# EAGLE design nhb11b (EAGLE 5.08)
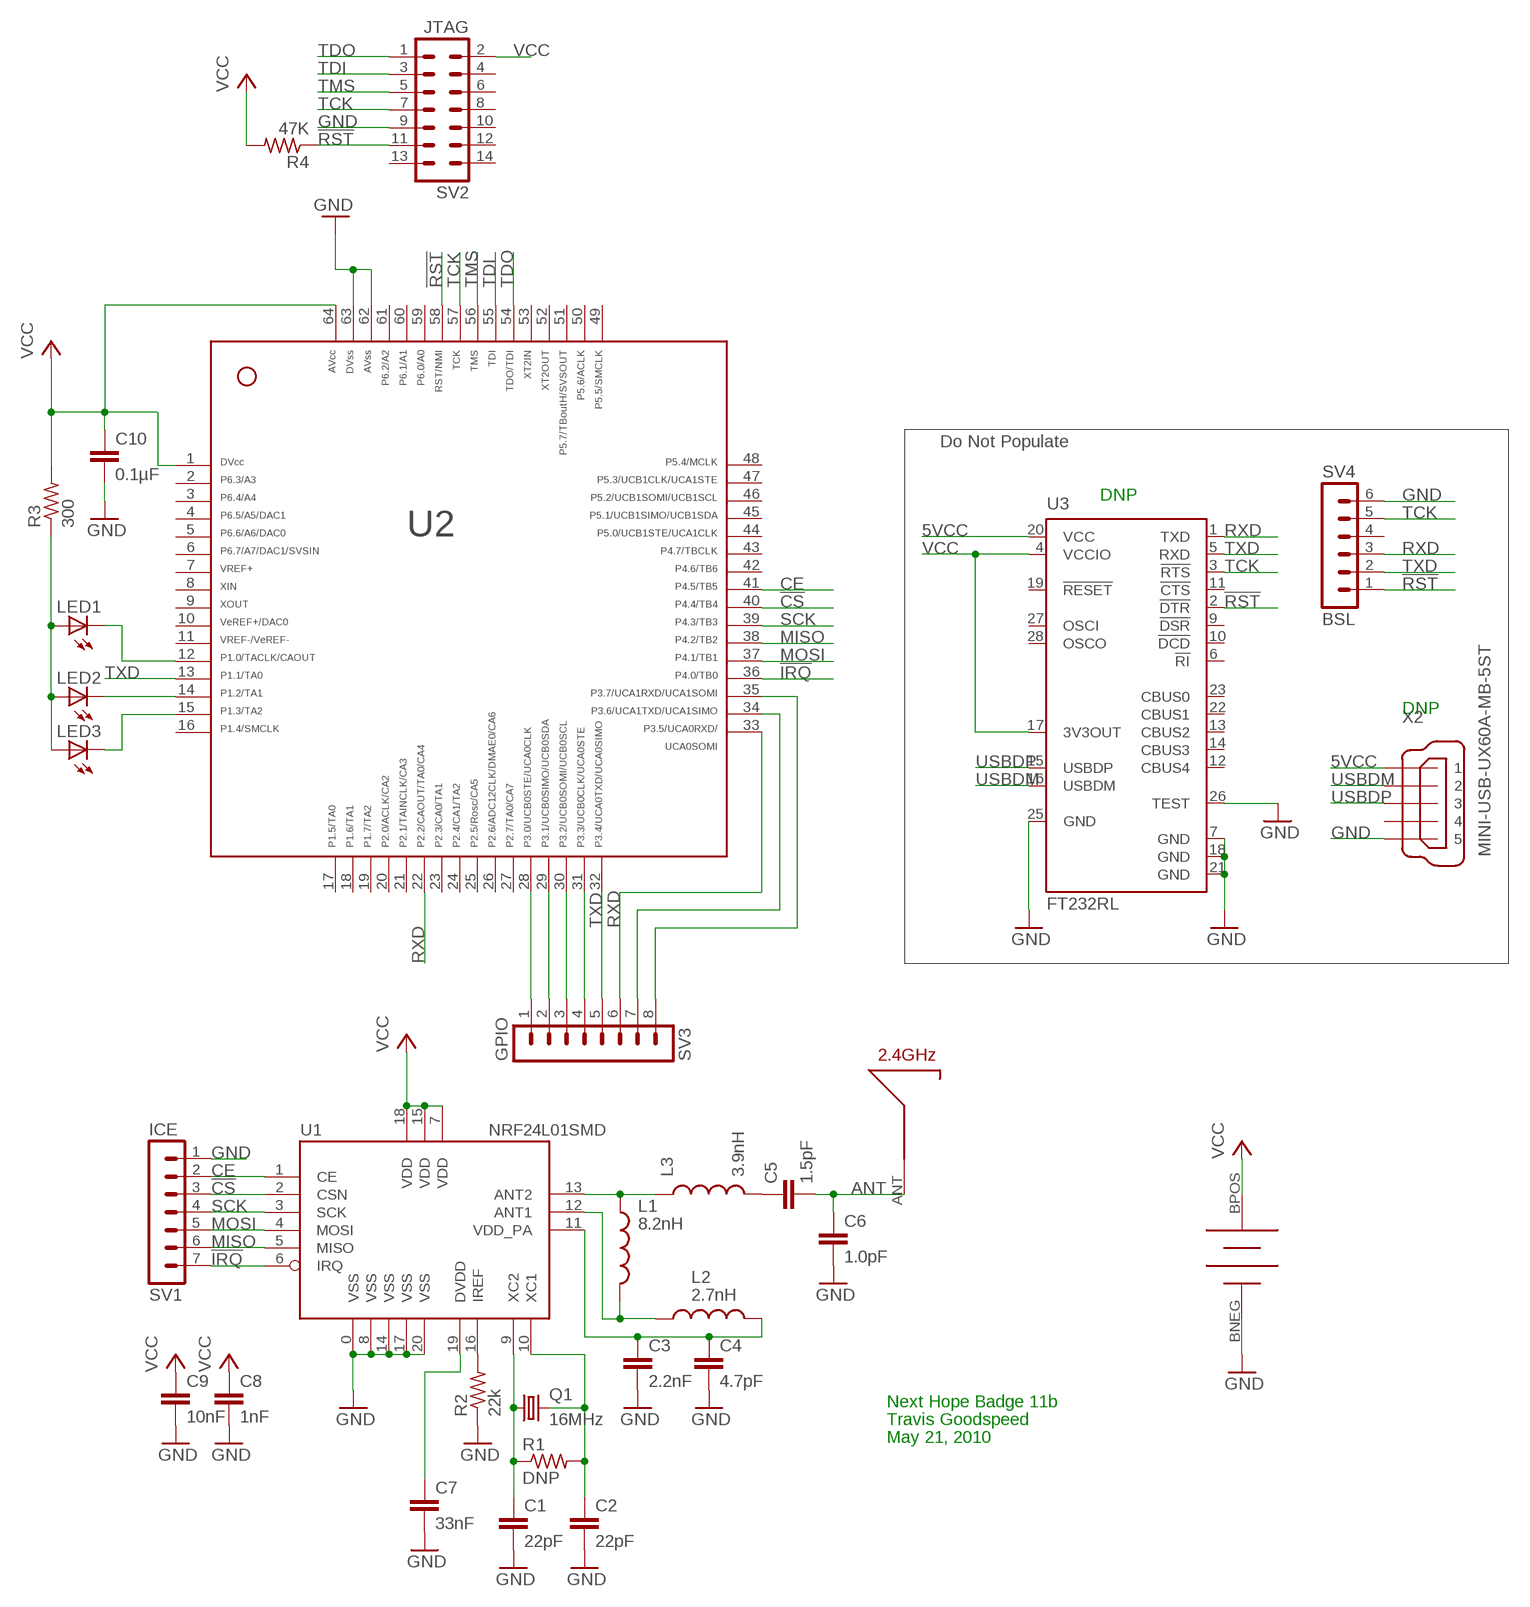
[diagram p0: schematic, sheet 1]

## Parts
C1  22pF  C-EUC0603  [C0603]
C2  22pF  C-EUC0603  [C0603]
C3  2.2nF  C-EUC0603  [C0603]
C4  4.7pF  C-EUC0603  [C0603]
C5  1.5pF  C-EUC0603  [C0603]
C6  1.0pF  C-EUC0603  [C0603]
C7  33nF  C-EUC0603  [C0603]
C8  1nF  C-EUC0603  [C0603]
C9  10nF  C-EUC0603  [C0603]
C10  0.1µF  C-EUC0603  [C0603]
L1  8.2nH  INDUCTOR0603  [0603]
L2  2.7nH  INDUCTOR0603  [0603]
L3  3.9nH  INDUCTOR0603  [0603]
LED1  LEDCHIPLED_0603  [CHIPLED_0603]
LED2  LEDCHIPLED_0603  [CHIPLED_0603]
LED3  LEDCHIPLED_0603  [CHIPLED_0603]
Q1  16MHz  CRYSTALSM49  [SM49]
R1  DNP  R-US_R0603  [R0603]
R2  22k  R-US_R0603  [R0603]
R3  300  R-US_R0603  [R0603]
R4  47K  R-US_R0603  [R0603]
SV1  ICE  MA07-1  [MA07-1]
SV2  JTAG  MA07-2  [MA07-2]
SV3  GPIO  MA08-1  [MA08-1]
SV4  BSL  MA06-1  [MA06-1]
U1  NRF24L01SMD  [QFN20]
U2  F261X---PM64  [PM/PAG64]
U3  FT232RL  [SSOP28]
U$1  CR2032  [CR2032]
U$2  ANT24  [ANT24]
X2  MINI-USB-UX60A-MB-5ST  [UX60A-MB-5ST]

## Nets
5VCC: U3.20(VCC) X2.1
!CS: SV1.3 U1.2(CSN) U2.40
!IRQ: SV1.7 U1.6(IRQ) U2.36
!RST: R4.1 SV2.11 SV4.1 U2.58 U3.2(!DTR)
ANT: C5.2 C6.1 U$2.ANT
CE: SV1.2 U1.1(CE) U2.41
GND: C1.2 C2.2 C3.2 C4.2 C6.2 C7.2 C8.2 C9.2 C10.2 R2.1 SV1.1 SV2.9 SV4.6 U1.0(VSS) U1.8(VSS) U1.14(VSS) U1.17(VSS) U1.20(VSS) U2.62 U2.63 U3.7(GND) U3.18(GND) U3.21(GND) U3.25(GND) U3.26(TEST) U$1.BNEG(BATGND) X2.5
MISO: SV1.6 U1.5(MISO) U2.38
MOSI: SV1.5 U1.4(MOSI) U2.37
N$1: C1.1 Q1.1 R1.1 U1.9(XC2)
N$2: C2.1 Q1.2 R1.2 U1.10(XC1)
N$3: R2.2 U1.16(IREF)
N$4: C7.1 U1.19(DVDD)
N$5: C3.1 C4.1 L2.2 U1.11(VDD_PA)
N$6: C5.1 L3.2
N$7: L1.2 L2.1 U1.12(ANT1)
N$8: SV3.1 U2.28
N$9: L1.1 L3.1 U1.13(ANT2)
N$10: LED1.A LED2.A LED3.A R3.1
N$11: SV3.2 U2.29
N$12: LED1.C U2.12
N$13: LED3.C U2.15
N$14: LED2.C U2.14
N$15: SV3.3 U2.30
N$16: SV3.4 U2.31
N$19: SV3.7 U2.34
N$23: SV3.8 U2.35
RXD: SV3.6 SV4.3 U2.22 U2.33 U3.1(TXD)
SCK: SV1.4 U1.3(SCK) U2.39
TCK: SV2.7 SV4.5 U2.57 U3.3(!RTS)
TDI: SV2.3 U2.55
TDO: SV2.1 U2.54
TMS: SV2.5 U2.56
TXD: SV3.5 SV4.2 U2.13 U2.32 U3.5(RXD)
USBDM: U3.16(USBDM) X2.2
USBDP: U3.15(USBDP) X2.3
VCC: C8.1 C9.1 C10.1 R3.2 R4.2 SV2.2 U1.7(VDD) U1.15(VDD) U1.18(VDD) U2.1 U2.64 U3.4(VCCIO) U3.17(3V3OUT) U$1.BPOS(BATVCC)
Unconnected: SV2.4 SV2.6 SV2.8 SV2.10 SV2.12 SV2.13 SV2.14 SV4.4 U2.2 U2.3 U2.4 U2.5 U2.6 U2.7 U2.8 U2.9 U2.10 U2.11 U2.16 U2.17 U2.18 U2.19 U2.20 U2.21 U2.23 U2.24 U2.25 U2.26 U2.27 U2.42 U2.43 U2.44 U2.45 U2.46 U2.47 U2.48 U2.49 U2.50 U2.51 U2.52 U2.53 U2.59 U2.60 U2.61 U3.6(!RI) U3.9(!DSR) U3.10(!DCD) U3.11(!CTS) U3.12(CBUS4) U3.13(CBUS2) U3.14(CBUS3) U3.19(!RESET) U3.22(CBUS1) U3.23(CBUS0) U3.27(OSCI) U3.28(OSCO) X2.4

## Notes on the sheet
- Do Not Populate
- DNP
- DNP
- Next Hope Badge 11b
- Travis Goodspeed
- May 21, 2010

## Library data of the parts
C1-C10 = rcl:C-EU: CAPACITOR, European symbol
L1-L3 = SparkFun:INDUCTOR: Inductors
LED1-LED3 = led:LED: LED
Q1 = crystal:CRYSTAL: CRYSTAL
R1-R4 = rcl:R-US_: RESISTOR, American symbol
SV1 = con-lstb:MA07-1: PIN HEADER
SV2 = con-lstb:MA07-2: PIN HEADER
SV3 = con-lstb:MA08-1: PIN HEADER
SV4 = con-lstb:MA06-1: PIN HEADER
U1 = SparkFun:NRF24L01: 2.4GHz Low Power Transceiver This is the very popular, low cost, very low power RF transceiver from Nordic Semiconductor. Simple SPI interface. SKU: COM-00690
U2 = TI_MSP430_v13:F261X---PM64: ***MSP430F261x***PM64
U3 = ftdichip:FT232R: Source: http://www.ftdichip.com/Documents/DataSheets/DS_FT232R_v104.pdf
U$1 = nhb:CR2032
U$2 = nhb:ANT24: 2.45GHz trace antenna.
X2 = con-hirose:MINI-USB-: MINI USB Connector Source: http://www.hirose.co.jp/cataloge_hp/e24000019.pdf

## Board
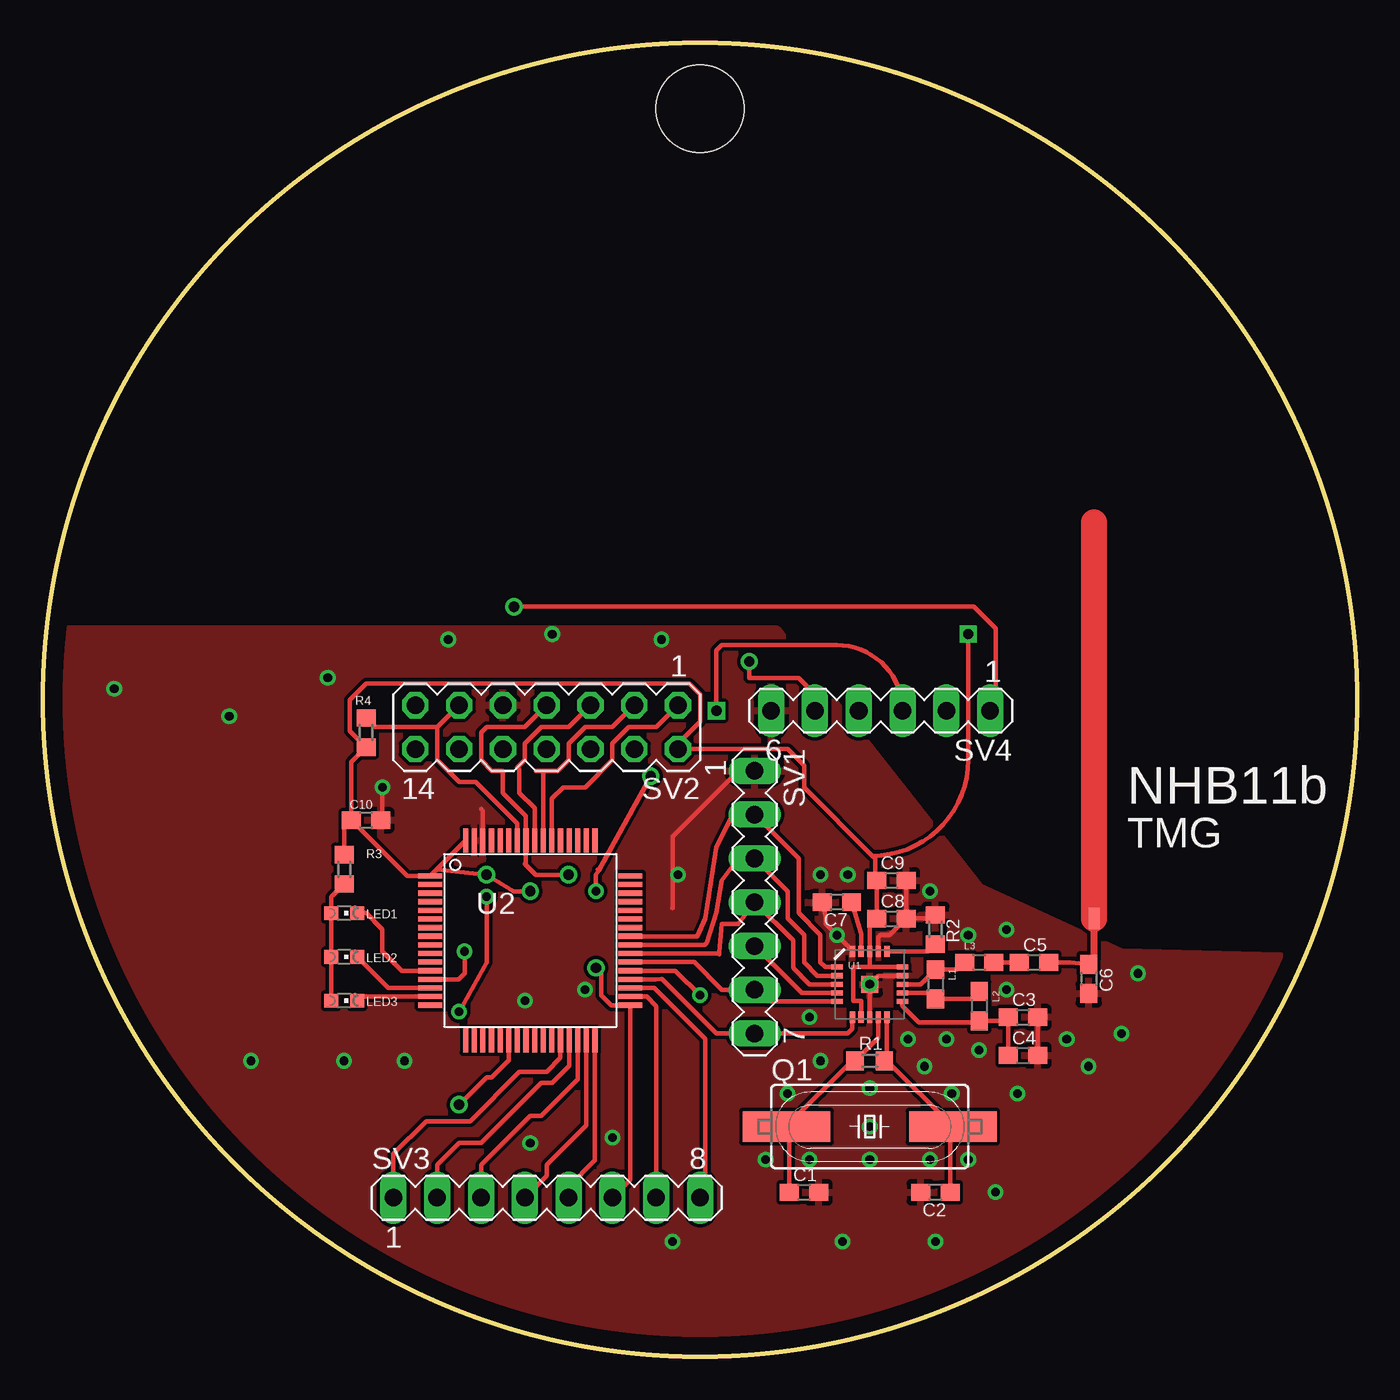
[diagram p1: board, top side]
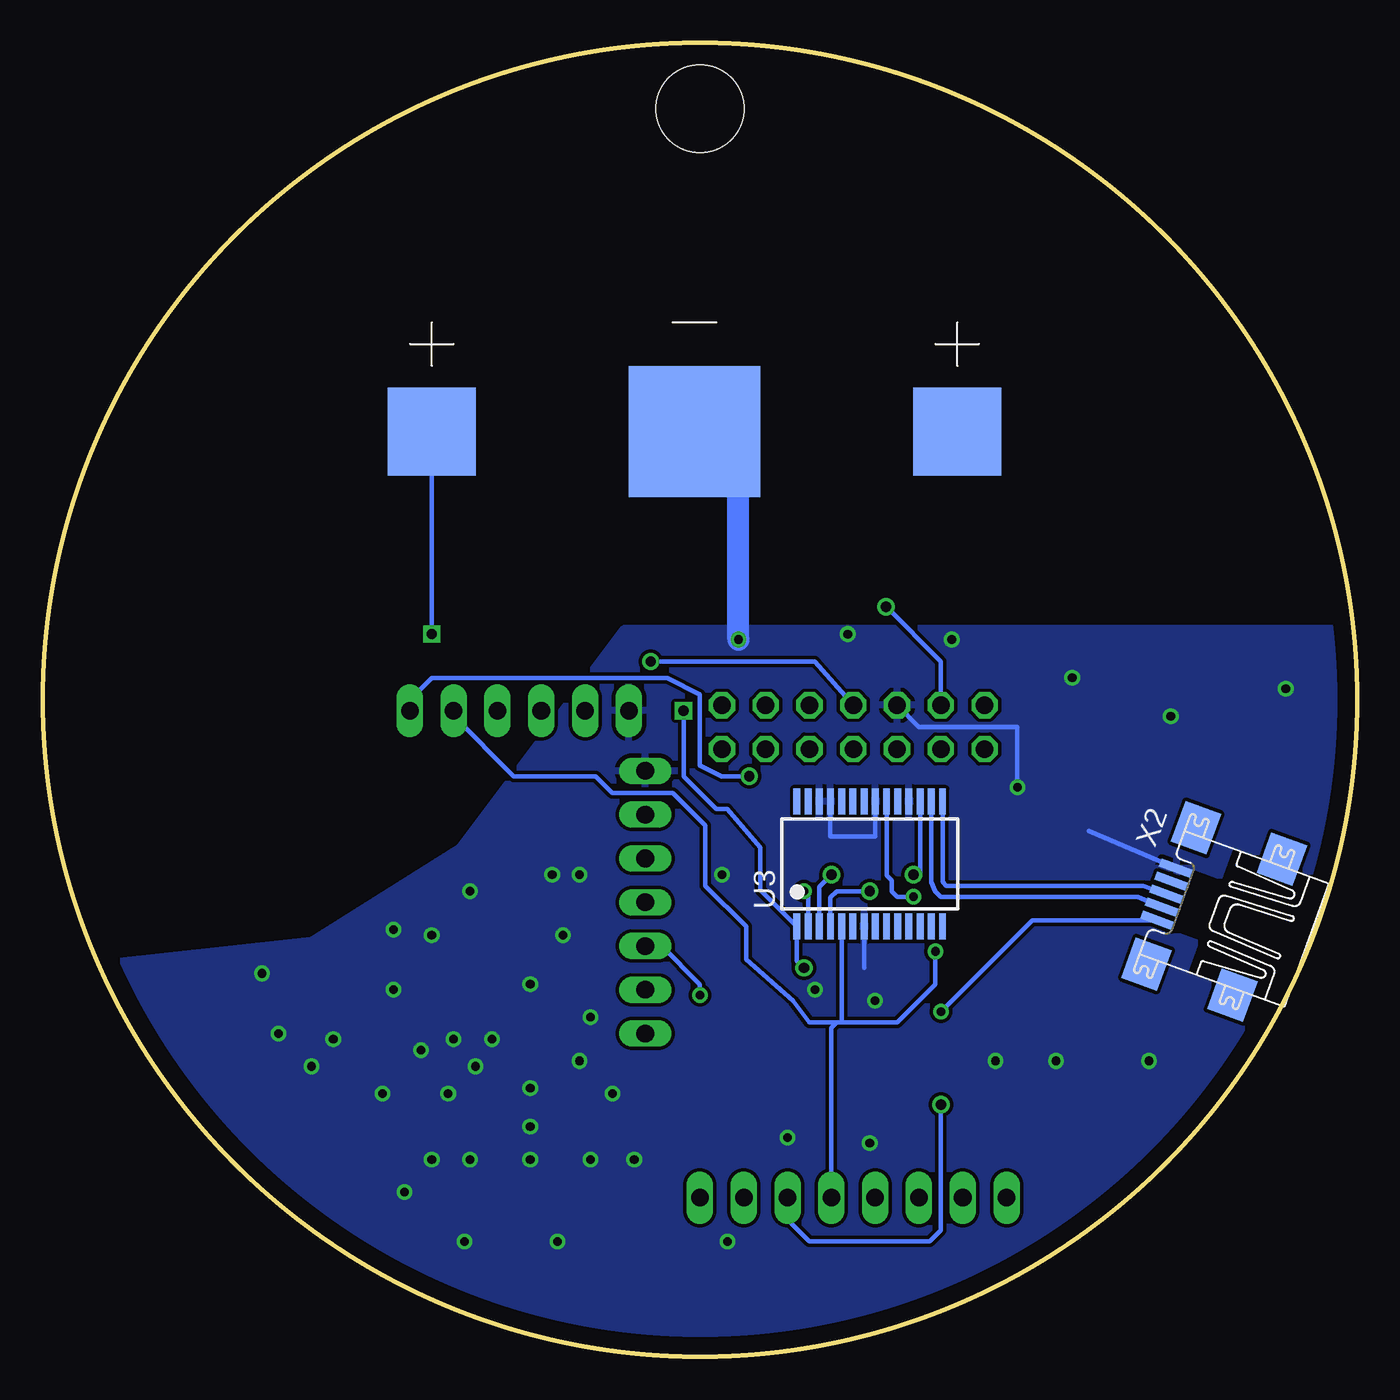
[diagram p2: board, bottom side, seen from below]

Size 76.2 x 76.2 mm. Coordinates in mm from the lower left corner, seen from the top.
Outline: circle at 38.1,38.1 radius 38.1
Copper layers (1*16): Top 0.035mm / dielectric 1.5mm / Bottom 0.035mm
Design rules "default *": minimum track width 10mil, minimum drill 8mil, track to track 8mil, track to pad 8mil, pad to pad 4mil, via to via 8mil, smd to smd 4mil, copper to edge 40mil, drill to drill 4mil, minimum pad ring 10mil, minimum via ring 8mil, stop-mask expansion 4mil, vias tented up to drill 0mil, thermal gap 10mil
Holes 5.08 mm at 38.1,72.39

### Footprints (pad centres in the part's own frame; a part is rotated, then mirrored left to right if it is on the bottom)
C0603 = smd 1.1 x 1: 1 -0.85,0; 2 0.85,0
0603 = smd 1.1 x 1: 1 -0.85,0; 2 0.85,0
CHIPLED_0603 = smd 0.8 x 0.8: A 0,-0.75; C 0,0.75
SM49 = smd 5.08 x 1.778: 1 -4.826,0; 2 4.826,0
R0603 = smd 1 x 1.1: 1 -0.85,0; 2 0.85,0
MA07-1 = drill 1.016 long: 1 -7.62,0; 2 -5.08,0; 3 -2.54,0; 4 0,0; 5 2.54,0; 6 5.08,0; 7 7.62,0
MA07-2 = drill 1.016 octagon: 1 -7.62,-1.27; 2 -7.62,1.27; 3 -5.08,-1.27; 4 -5.08,1.27; 5 -2.54,-1.27; 6 -2.54,1.27; 7 0,-1.27; 8 0,1.27; 9 2.54,-1.27; 10 2.54,1.27; 11 5.08,-1.27; 12 5.08,1.27; 13 7.62,-1.27; 14 7.62,1.27
MA08-1 = drill 1.016 long: 1 -8.89,0; 2 -6.35,0; 3 -3.81,0; 4 -1.27,0; 5 1.27,0; 6 3.81,0; 7 6.35,0; 8 8.89,0
MA06-1 = drill 1.016 long: 1 -6.35,0; 2 -3.81,0; 3 -1.27,0; 4 1.27,0; 5 3.81,0; 6 6.35,0
QFN20 = smd 1 x 1: 0 0,0 | smd 0.65 x 0.3: 1 -1.9,1; 2 -1.9,0.5; 3 -1.9,0; 4 -1.9,-0.5; 5 -1.9,-1; 11 1.9,-1; 12 1.9,-0.5; 13 1.9,0; 14 1.9,0.5; 15 1.9,1 | smd 0.3 x 0.65: 6 -1,-1.9; 7 -0.5,-1.9; 8 0,-1.9; 9 0.5,-1.9; 10 1,-1.9; 16 1,1.9; 17 0.5,1.9; 18 0,1.9; 19 -0.5,1.9; 20 -1,1.9
PM/PAG64 = smd 1.4 x 0.3: 1 -5.8,3.75; 2 -5.8,3.25; 3 -5.8,2.75; 4 -5.8,2.25; 5 -5.8,1.75; 6 -5.8,1.25; 7 -5.8,0.75; 8 -5.8,0.25; 9 -5.8,-0.25; 10 -5.8,-0.75; 11 -5.8,-1.25; 12 -5.8,-1.75; 13 -5.8,-2.25; 14 -5.8,-2.75; 15 -5.8,-3.25; 16 -5.8,-3.75; 33 5.8,-3.75; 34 5.8,-3.25; 35 5.8,-2.75; 36 5.8,-2.25; 37 5.8,-1.75; 38 5.8,-1.25; 39 5.8,-0.75; 40 5.8,-0.25; 41 5.8,0.25; 42 5.8,0.75; 43 5.8,1.25; 44 5.8,1.75; 45 5.8,2.25; 46 5.8,2.75; 47 5.8,3.25; 48 5.8,3.75 | smd 0.3 x 1.4: 17 -3.75,-5.8; 18 -3.25,-5.8; 19 -2.75,-5.8; 20 -2.25,-5.8; 21 -1.75,-5.8; 22 -1.25,-5.8; 23 -0.75,-5.8; 24 -0.25,-5.8; 25 0.25,-5.8; 26 0.75,-5.8; 27 1.25,-5.8; 28 1.75,-5.8; 29 2.25,-5.8; 30 2.75,-5.8; 31 3.25,-5.8; 32 3.75,-5.8; 49 3.75,5.8; 50 3.25,5.8; 51 2.75,5.8; 52 2.25,5.8; 53 1.75,5.8; 54 1.25,5.8; 55 0.75,5.8; 56 0.25,5.8; 57 -0.25,5.8; 58 -0.75,5.8; 59 -1.25,5.8; 60 -1.75,5.8; 61 -2.25,5.8; 62 -2.75,5.8; 63 -3.25,5.8; 64 -3.75,5.8
SSOP28 = smd 0.4 x 1.5: 1 -4.225,-3.625; 2 -3.575,-3.625; 3 -2.925,-3.625; 4 -2.275,-3.625; 5 -1.625,-3.625; 6 -0.975,-3.625; 7 -0.325,-3.625; 8 0.325,-3.625; 9 0.975,-3.625; 10 1.625,-3.625; 11 2.275,-3.625; 12 2.925,-3.625; 13 3.575,-3.625; 14 4.225,-3.625; 15 4.225,3.625; 16 3.575,3.625; 17 2.925,3.625; 18 2.275,3.625; 19 1.625,3.625; 20 0.975,3.625; 21 0.325,3.625; 22 -0.325,3.625; 23 -0.975,3.625; 24 -1.625,3.625; 25 -2.275,3.625; 26 -2.925,3.625; 27 -3.575,3.625; 28 -4.225,3.625
CR2032 = smd 7.62 x 7.62: BNEG 0,0 | smd 5.08 x 5.08: BPOS -15.24,0; BPOS2 15.24,0
ANT24 = smd 0.635 x 1.27: ANT 0,0
UX60A-MB-5ST = smd 2 x 0.5: 1 2.25,1.6; 2 2.25,0.8; 3 2.25,0; 4 2.25,-0.8; 5 2.25,-1.6 | smd 2.2 x 2.5: M1 -3.3,-4.2; M2 -3.3,4.2; M3 2,4.2; M4 2,-4.2

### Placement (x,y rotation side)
C1  44.13,9.53 0 top
C2  51.75,9.53 180 top
C3  56.83,19.69 0 top
C4  56.83,17.46 0 top
C5  57.47,22.86 0 top
C6  60.64,21.91 270 top
C7  46.04,26.35 180 top
C8  49.21,25.4 0 top
C9  49.21,27.62 0 top
C10  18.73,31.12 0 top
L1  51.75,21.59 270 top
L2  54.29,20.32 270 top
L3  54.29,22.86 0 top
LED1  17.46,25.72 270 top
LED2  17.46,23.18 270 top
LED3  17.46,20.64 270 top
Q1  47.94,13.34 0 top
R1  47.94,17.15 0 top
R2  51.75,24.77 270 top
R3  17.46,28.26 90 top
R4  18.73,36.2 270 top
SV1  41.27,26.35 270 top
SV2  29.21,36.51 180 top
SV3  29.21,9.21 0 top
SV4  48.58,37.47 180 top
U1  47.94,21.59 0 top
U2  28.26,24.13 0 top
U3  28.26,28.58 0 bottom
U$1  38.42,53.66 0 bottom
U$2  60.96,25.4 0 top
X2  8.89,26.04 160 bottom

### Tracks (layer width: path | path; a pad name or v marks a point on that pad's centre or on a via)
5VCC  (via drill 0.5 pad 0.25)
  Top 0.254: v25.72,26.67 25.72,22.86 v24.13,20
  Bottom 0.254: v24.13,20 18.83,25.3 X2.1 | U3.20 27.28,27.92 26.99,27.62 26.99,26.99 26.67,26.67 v25.72,26.67
!CS
  Top 0.254: U1.2 44.9,22.09 44.13,22.86 44.13,24.45 43.18,25.4 43.18,26.99 SV1.3 40.32,28.89 39.37,27.62 39.05,25.72 38.49,24 38.37,23.88 U2.40
!IRQ
  Top 0.254: U1.6 46.94,19 46.67,18.73 SV1.7 39.05,18.73 35.88,21.91 35.53,21.88 U2.36
!RST  (via drill 0.5 pad 0.25, 0.6)
  Top 0.254: 22.86,36.51 22.86,34.61 24.13,33.34 25.08,33.34 27.51,30.91 U2.58 | SV2.11 22.86,36.51 | 22.86,36.51 19.27,36.51 R4.1 | v32.07,26.99 32.07,27.94 32.22,28.21 | 32.22,28.21 v35.24,33.65 | 32.22,28.21 32.17,28.26 | v27.3,43.5 53.98,43.5 55.24,42.23 55.24,37.78 SV4.1
  Bottom 0.254: U3.2 31.83,26.75 v32.07,26.99 | v35.24,33.65 36.83,33.65 38.1,34.29 38.1,38.42 40.01,39.37 53.66,39.37 54.93,38.1 SV4.1 | SV2.11 24.13,40.32 v27.3,43.5
ANT
  Top 0.254: C5.2 59.59,22.86 C6.1
  Top 0.406: U$2.ANT 60.96,23.07 C6.1
CE
  Top 0.254: U1.1 45.35,22.59 45.09,22.86 45.09,24.45 43.81,25.72 43.81,28.89 SV1.2 40.01,31.43 39.05,29.53 38.42,25.4 37.94,24.38 U2.41
GND  (via drill 0.5, 0.5 pad 0.25)
  Top 0.254: U1.14 48.44,22.09 U1.0 U1.8 | C8.2 C9.2 | U1.17 48.44,24.31 48.58,24.45 49.11,24.45 C8.2 | C8.2 51.54,25.4 R2.1 | C4.2 C3.2 | U1.20 46.94,23.54 v46.04,24.45 45.4,25.08 45.4,25.5 C7.2 | 36.49,26.01 36.51,26.03 36.51,30.16 40.32,33.97 SV1.1 | v19.68,33.02 19.68,31.22 C10.2 | U2.62 25.51,31.64 25.4,31.75
  Bottom 0.254: SV2.9 25.4,36.51 19.68,36.51 v19.68,33.02 | X2.5 15.56,30.48 | U3.21 27.93,30.16 30.53,30.16 U3.25 | U3.7 28.58,22.55 28.58,22.54
  Bottom 0.406: 35.88,53.66 U$1.BNEG
  Bottom 1.27: v35.88,41.59 35.88,53.66
  other vias: 47.94,21.59 53.66,24.45 45.09,27.94 46.67,27.94 51.44,26.99 55.88,24.77 55.88,21.27 44.45,19.69 50.16,18.42 52.39,18.42 54.29,17.78 51.12,16.83 41.91,11.43 43.18,15.24 45.09,17.15 47.94,15.56 47.94,13.34 44.45,11.43 47.94,11.43 51.44,11.43 53.66,11.43 52.7,15.24 36.51,6.67 4.13,38.74 46.35,6.67 29.53,41.91 51.75,6.67 10.79,37.15 55.24,9.53 12.06,17.15 63.5,22.23 60.64,16.83 62.55,18.73 59.37,18.42 56.52,15.24 23.5,41.59 28.26,12.38 33.02,12.7 20.96,17.15 17.46,17.15 16.51,39.37 31.43,21.27 36.83,27.94 27.94,20.64
  pour Bottom: -0.95,42.23 42.55,42.23 52.07,29.53 60.64,24.13 75.25,22.54 75.25,-0.32 -0.95,-0.32
  pour Top: -0.95,42.23 42.55,42.23 54.29,27.31 62.55,23.5 75.25,23.18 75.25,-0.63 -0.95,-0.63
MISO
  Top 0.254: U1.5 41.96,20.59 SV1.6 39.37,21.27 37.76,22.88 U2.38
MOSI  (via drill 0.5 pad 0.25)
  Top 0.254: U1.4 44,21.09 SV1.5 | U2.37 36.67,22.38 v38.1,20.96
  Bottom 0.254: v38.1,20.96 38.1,21.59 40.32,23.81 SV1.5
N$1
  Top 0.254: U1.9 48.44,18.49 R1.1 46.93,17.14 Q1.1 43.28,13.17 C1.1
N$2
  Top 0.254: 48.94,17.3 U1.10 | 48.94,17.3 R1.2 | 48.94,17.3 48.94,17.16 Q1.2 52.6,13.17 C2.1
N$3
  Top 0.254: U1.16 51.33,23.49 R2.2
N$4
  Top 0.254: U1.19 47.44,24.53 C7.1
N$5
  Top 0.254: U1.11 49.84,20.32 50.8,19.37 54.19,19.37 L2.2 55.77,19.47 C3.1 C4.1
N$6
  Top 0.254: C5.1 L3.2
N$7
  Top 0.254: U1.12 51.4,21.09 L1.2 53.86,20.74 L2.1
N$8
  Top 0.254: U2.28 30.01,17.31 29.21,16.51 27.62,16.51 24.77,13.65 22.23,13.65 20.32,11.75 SV3.1
N$9
  Top 0.254: U1.13 50.9,21.59 L1.1 53.02,22.44 L3.1
N$10
  Top 0.254: R3.1 16.71,26.66 LED1.A LED2.A LED3.A
N$11
  Top 0.254: U2.29 30.51,16.85 29.53,15.87 28.89,15.87 25.4,12.38 24.13,12.38 22.86,11.11 SV3.2
N$12
  Top 0.254: LED1.C 18.73,25.72 19.68,24.76 19.68,23.49 20.8,22.38 U2.12
N$13
  Top 0.254: U2.15 18.46,20.88 LED3.C
N$14
  Top 0.254: 18.37,23.01 LED2.C 20.01,21.38 U2.14
N$15
  Top 0.254: U2.30 31.01,16.08 28.89,13.97 28.26,13.97 25.4,11.11 SV3.3
N$16
  Top 0.254: U2.31 31.51,13.41 29.21,11.11 29.21,10.48 SV3.4
N$19
  Top 0.254: U2.34 35,20.88 35.56,20.32 SV3.7
N$23
  Top 0.254: U2.35 35.45,21.38 38.42,18.42 38.42,9.52 SV3.8
RXD  (via drill 0.6)
  Top 0.254: 24.01,14.6 v24.13,14.6 25.72,16.19 26.03,16.19 27.01,17.17 U2.22 | v39.05,37.46 39.05,40.96 39.37,41.28 46.04,41.28 arc-90 SV4.3 | SV3.6 34.06,10.24 U2.33 32.96,20.38 32.38,20.96 32.38,22.23 v32.07,22.54
  Bottom 0.254: v24.13,14.6 24.13,7.3 24.77,6.67 31.75,6.67 33.02,7.94 SV3.6 | v39.05,37.46 39.05,33.65 37.15,31.75 36.51,31.75 34.61,29.53 34.61,27.07 U3.1 32.48,22.96 v32.07,22.54
SCK
  Top 0.254: U1.3 44.45,21.59 43.5,22.54 43.5,24.13 SV1.4 40.32,25.08 39.37,25.08 39.22,23.45 | 39.22,23.45 39.21,23.33 | U2.39 39.15,23.38 39.22,23.45
TCK  (via drill 0.6)
  Top 0.254: SV2.7 27.94,36.51 25.72,36.51 25.4,36.2 25.4,34.61 26.03,33.97 26.67,33.97 26.67,32.7 28.01,31.37 U2.57 28.01,28.64 27.94,28.57 28.58,27.94 v30.48,27.94 | SV4.5 44.77,38.42 43.81,39.37 40.96,39.37 v40.96,40.32
  Bottom 0.254: v40.96,40.32 31.43,40.32 SV2.7 | U3.3 31.18,27.24 v30.48,27.94
TDI
  Top 0.254: 28.89,33.97 28.58,33.97 | 28.89,33.97 29.84,33.97 30.48,34.61 30.48,35.56 31.43,36.51 33.02,36.51 SV2.3 | U2.55 29.01,33.86 28.89,33.97
TDO
  Top 0.254: SV2.1 35.56,36.51 33.97,36.51 33.02,35.56 33.02,34.61 31.43,33.02 30.16,33.02 29.51,32.36 U2.54
TMS
  Top 0.254: SV2.5 30.48,36.51 28.89,36.51 27.94,35.56 27.94,34.61 27.51,34.17 27.62,34.06 27.62,32.7 28.51,31.82 U2.56
TXD  (via drill 0.5 pad 0.25)
  Top 0.254: 24.43,23.51 v24.45,23.49 24.45,22.23 24.1,21.88 U2.13 | SV3.5 30.48,9.84 32.01,11.37 U2.32
  Bottom 0.254: v24.45,23.49 24.45,21.59 26.67,19.37 29.84,19.37 | 30.16,19.37 31.75,19.37 32.7,20.64 35.43,23.05 35.43,24.95 37.78,27.3 37.78,30.8 39.69,32.7 43.18,32.7 44.13,33.65 48.9,33.65 52.39,37.15 SV4.2 | 30.16,19.37 29.84,19.37 | 30.16,19.37 30.48,19.05 SV3.5 | U3.5 29.88,19.41 29.84,19.37
USBDM
  Bottom 0.254: U3.16 24.68,27.54 24.45,26.99 24.13,26.67 12.7,26.67 X2.2
USBDP
  Bottom 0.254: U3.15 24.03,27.53 23.81,27.3 12.38,27.3 X2.3
VCC  (via drill 0.6)
  Top 0.254: 47.94,22.59 46.99,22.59 46.99,20.64 47.44,20.64 U1.7 | 47.94,22.59 U1.15 | 47.94,22.59 U1.18 47.94,24.98 C8.1 C9.1 48.26,27.73 48.26,28.89 48.1,29.05 | R3.2 17.46,30.69 C10.1 | C10.1 17.88,34.49 R4.2 17.78,36.3 17.78,38.1 18.73,39.05 37.47,39.05 38.1,38.42 38.1,36.83 36.83,35.56 SV2.2 43.18,35.24 44.13,34.29 44.13,33.02 48.1,29.05 | v53.66,41.91 53.66,34.61 arc-90 48.1,29.05 | C10.1 21.12,27.88 U2.1 22.85,28.27 | 22.85,28.27 U2.64 | v28.26,26.99 27.3,26.99 v25.72,27.94 22.86,28.26 22.85,28.27
  Bottom 0.254: v53.66,41.91 U$1.BPOS | U3.4 30.53,26.62 30.16,26.99 v28.26,26.99 | U3.17 25.33,28.01 v25.72,27.94

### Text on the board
tNames: NHB11b | TMG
